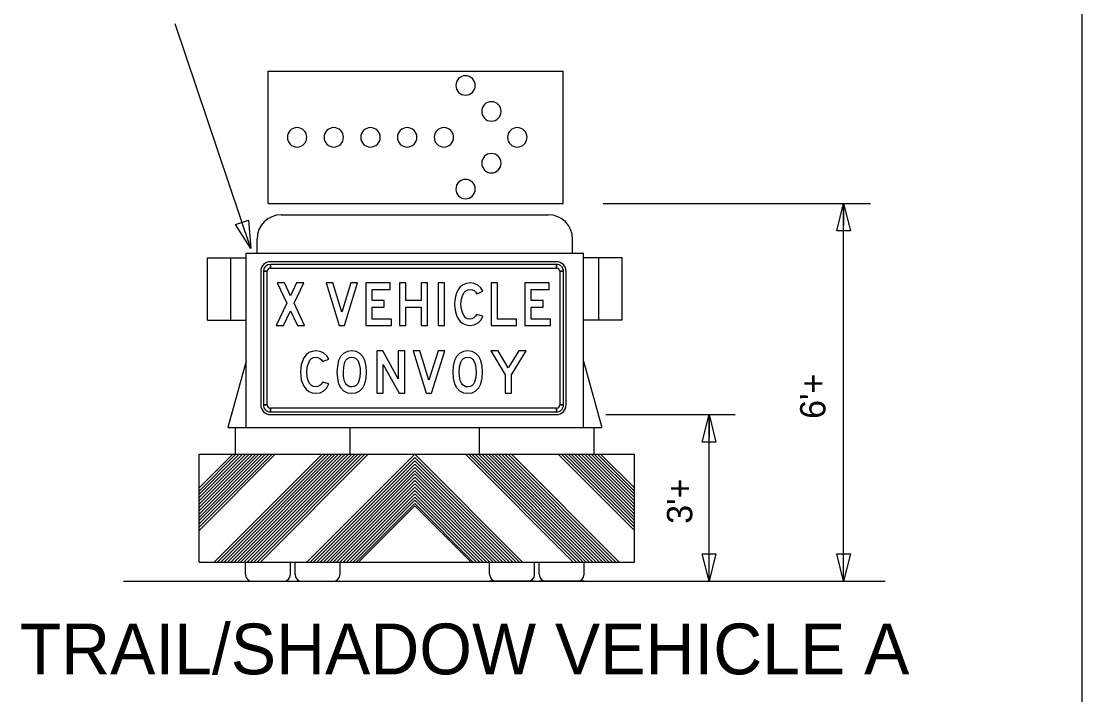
# Model space of a CAD drawing. Extents: x 1373848 to 1374003, y 380642 to 381248.
# Drawn here: x 1373929.4 to 1373954.48, y 381055.63 to 381071.55 of the extents above; entities that cross this region are included whole.
import ezdxf

# ---------------------------------------------------------------- set-up
doc = ezdxf.new("R2010")
doc.units = 0
doc.layers.add('Working Level 1', color=7, linetype='Continuous')

msp = doc.modelspace()

# ---------------------------------------------------------------- linework, layer by layer
at = {"layer": 'Working Level 1'}
for p, q in [((1373954.481, 381081.277), (1373954.481, 380977.045)), ((1373934.824, 381066.18), (1373933.038, 381071.487)), ((1373935.233, 381070.37), (1373942.211, 381070.37)), ((1373935.233, 381067.242), (1373935.233, 381070.37)), ((1373942.211, 381067.242), (1373942.211, 381070.37)), ((1373935.233, 381067.242), (1373942.211, 381067.242)), ((1373943.157, 381067.242), (1373949.484, 381067.242)), ((1373948.848, 381058.31), (1373948.848, 381067.242)), ((1373948.848, 381067.242), (1373948.848, 381066.718)), ((1373935.548, 381066.974), (1373941.862, 381066.974)), ((1373934.974, 381066.071), (1373934.974, 381066.4)), ((1373942.436, 381066.071), (1373942.436, 381066.4)), ((1373933.803, 381064.487), (1373933.803, 381065.954)), ((1373933.803, 381065.954), (1373934.714, 381065.954)), ((1373934.354, 381064.487), (1373934.354, 381065.954)), ((1373934.714, 381061.944), (1373934.714, 381066.071)), ((1373934.714, 381066.071), (1373942.696, 381066.071)), ((1373942.696, 381061.944), (1373942.696, 381066.071)), ((1373943.607, 381065.954), (1373942.696, 381065.954)), ((1373943.055, 381064.487), (1373943.055, 381065.954)), ((1373943.607, 381064.487), (1373943.607, 381065.954)), ((1373942.059, 381065.864), (1373935.288, 381065.864)), ((1373935.288, 381065.713), (1373935.288, 381065.801)), ((1373942.059, 381065.801), (1373942.059, 381065.713)), ((1373935.062, 381065.638), (1373935.062, 381062.478)), ((1373935.125, 381065.638), (1373935.213, 381065.638)), ((1373942.135, 381065.638), (1373942.222, 381065.638)), ((1373942.285, 381062.478), (1373942.285, 381065.638)), ((1373933.803, 381064.487), (1373934.714, 381064.487)), ((1373943.607, 381064.487), (1373942.696, 381064.487)), ((1373934.714, 381063.516), (1373934.282, 381061.944)), ((1373942.696, 381063.516), (1373943.128, 381061.944)), ((1373935.213, 381062.478), (1373935.125, 381062.478)), ((1373935.288, 381062.315), (1373935.288, 381062.403)), ((1373942.059, 381062.403), (1373942.059, 381062.315)), ((1373942.222, 381062.478), (1373942.135, 381062.478)), ((1373935.288, 381062.252), (1373942.059, 381062.252)), ((1373943.223, 381062.252), (1373946.284, 381062.252)), ((1373945.667, 381058.31), (1373945.667, 381062.252)), ((1373945.667, 381062.252), (1373945.667, 381061.72)), ((1373934.282, 381061.944), (1373943.128, 381061.944)), ((1373934.461, 381061.314), (1373934.461, 381061.944)), ((1373937.173, 381061.314), (1373937.173, 381061.933)), ((1373940.237, 381061.314), (1373940.237, 381061.933)), ((1373942.949, 381061.314), (1373942.949, 381061.944)), ((1373933.604, 381061.314), (1373943.899, 381061.314)), ((1373933.604, 381061.314), (1373943.899, 381061.314)), ((1373933.604, 381061.314), (1373943.899, 381061.314)), ((1373933.604, 381061.314), (1373943.899, 381061.314)), ((1373933.604, 381058.764), (1373933.604, 381061.314)), ((1373933.604, 381060.516), (1373934.402, 381061.314)), ((1373933.604, 381059.588), (1373935.33, 381061.314)), ((1373933.604, 381059.666), (1373935.252, 381061.314)), ((1373933.604, 381059.744), (1373935.174, 381061.314)), ((1373933.604, 381059.821), (1373935.097, 381061.314)), ((1373933.604, 381059.899), (1373935.019, 381061.314)), ((1373933.604, 381059.977), (1373934.941, 381061.314)), ((1373933.604, 381060.054), (1373934.864, 381061.314)), ((1373933.604, 381060.132), (1373934.786, 381061.314)), ((1373933.604, 381060.211), (1373934.707, 381061.314)), ((1373933.604, 381060.289), (1373934.629, 381061.314)), ((1373933.604, 381060.366), (1373934.552, 381061.314)), ((1373933.604, 381060.444), (1373934.474, 381061.314)), ((1373933.604, 381059.51), (1373935.405, 381061.312)), ((1373933.963, 381058.764), (1373936.513, 381061.314)), ((1373934.041, 381058.764), (1373936.591, 381061.314)), ((1373934.119, 381058.764), (1373936.669, 381061.314)), ((1373934.197, 381058.764), (1373936.747, 381061.314)), ((1373934.274, 381058.764), (1373936.824, 381061.314)), ((1373934.352, 381058.764), (1373936.902, 381061.314)), ((1373934.43, 381058.764), (1373936.98, 381061.314)), ((1373934.508, 381058.764), (1373937.058, 381061.314)), ((1373934.585, 381058.764), (1373937.135, 381061.314)), ((1373934.663, 381058.764), (1373937.213, 381061.314)), ((1373934.742, 381058.764), (1373937.291, 381061.314)), ((1373934.819, 381058.764), (1373937.368, 381061.314)), ((1373934.897, 381058.764), (1373937.446, 381061.314)), ((1373934.975, 381058.764), (1373937.523, 381061.313)), ((1373935.052, 381058.764), (1373937.602, 381061.314)), ((1373936.155, 381058.764), (1373938.705, 381061.314)), ((1373936.233, 381058.764), (1373938.705, 381061.236)), ((1373936.311, 381058.764), (1373938.705, 381061.158)), ((1373941.255, 381058.764), (1373938.705, 381061.314)), ((1373941.173, 381058.768), (1373938.705, 381061.236)), ((1373941.1, 381058.764), (1373938.705, 381061.158)), ((1373942.451, 381058.764), (1373939.901, 381061.314)), ((1373942.528, 381058.764), (1373939.98, 381061.313)), ((1373942.607, 381058.764), (1373940.057, 381061.314)), ((1373942.685, 381058.764), (1373940.135, 381061.314)), ((1373942.762, 381058.764), (1373940.212, 381061.314)), ((1373942.84, 381058.764), (1373940.29, 381061.314)), ((1373942.918, 381058.764), (1373940.368, 381061.314)), ((1373942.995, 381058.764), (1373940.445, 381061.314)), ((1373943.073, 381058.764), (1373940.523, 381061.314)), ((1373943.151, 381058.764), (1373940.601, 381061.314)), ((1373943.229, 381058.764), (1373940.679, 381061.314)), ((1373943.306, 381058.764), (1373940.756, 381061.314)), ((1373943.384, 381058.764), (1373940.834, 381061.314)), ((1373943.462, 381058.764), (1373940.913, 381061.314)), ((1373943.54, 381058.764), (1373940.99, 381061.314)), ((1373943.899, 381059.51), (1373942.098, 381061.312)), ((1373943.899, 381059.588), (1373942.173, 381061.314)), ((1373943.899, 381059.666), (1373942.251, 381061.314)), ((1373943.899, 381059.744), (1373942.329, 381061.314)), ((1373943.899, 381059.821), (1373942.406, 381061.314)), ((1373943.899, 381059.899), (1373942.484, 381061.314)), ((1373943.899, 381059.977), (1373942.563, 381061.314)), ((1373943.899, 381060.054), (1373942.64, 381061.314)), ((1373943.899, 381060.132), (1373942.718, 381061.314)), ((1373943.899, 381060.211), (1373942.796, 381061.314)), ((1373943.899, 381060.289), (1373942.874, 381061.314)), ((1373943.899, 381060.366), (1373942.951, 381061.314)), ((1373943.899, 381060.444), (1373943.029, 381061.314)), ((1373943.899, 381060.516), (1373943.101, 381061.314)), ((1373943.899, 381058.764), (1373943.899, 381061.314)), ((1373936.389, 381058.764), (1373938.705, 381061.08)), ((1373936.466, 381058.764), (1373938.705, 381061.003)), ((1373936.544, 381058.764), (1373938.705, 381060.925)), ((1373941.021, 381058.764), (1373938.705, 381061.08)), ((1373940.944, 381058.764), (1373938.705, 381061.003)), ((1373940.866, 381058.764), (1373938.705, 381060.925)), ((1373936.622, 381058.764), (1373938.705, 381060.847)), ((1373936.699, 381058.764), (1373938.705, 381060.77)), ((1373936.777, 381058.764), (1373938.705, 381060.692)), ((1373940.788, 381058.764), (1373938.705, 381060.847)), ((1373940.711, 381058.764), (1373938.705, 381060.77)), ((1373940.633, 381058.764), (1373938.705, 381060.692)), ((1373936.855, 381058.764), (1373938.705, 381060.614)), ((1373936.933, 381058.764), (1373938.705, 381060.536)), ((1373937.01, 381058.764), (1373938.705, 381060.459)), ((1373940.555, 381058.764), (1373938.705, 381060.614)), ((1373940.477, 381058.764), (1373938.705, 381060.536)), ((1373940.4, 381058.764), (1373938.705, 381060.459)), ((1373937.088, 381058.764), (1373938.705, 381060.38)), ((1373937.167, 381058.764), (1373938.705, 381060.302)), ((1373937.244, 381058.764), (1373938.705, 381060.225)), ((1373937.321, 381058.764), (1373938.705, 381060.148)), ((1373940.322, 381058.764), (1373938.705, 381060.38)), ((1373940.244, 381058.764), (1373938.705, 381060.302)), ((1373940.167, 381058.764), (1373938.705, 381060.225)), ((1373940.089, 381058.764), (1373938.705, 381060.148)), ((1373937.387, 381058.779), (1373938.705, 381060.097)), ((1373940.038, 381058.764), (1373938.705, 381060.097)), ((1373933.604, 381058.764), (1373943.899, 381058.764)), ((1373933.604, 381058.764), (1373943.899, 381058.764)), ((1373933.604, 381058.764), (1373943.899, 381058.764)), ((1373933.604, 381058.764), (1373943.899, 381058.764)), ((1373934.698, 381058.475), (1373934.698, 381058.764)), ((1373935.762, 381058.475), (1373935.762, 381058.764)), ((1373935.872, 381058.475), (1373935.872, 381058.764)), ((1373936.936, 381058.475), (1373936.936, 381058.764)), ((1373940.474, 381058.475), (1373940.474, 381058.764)), ((1373941.538, 381058.475), (1373941.538, 381058.764)), ((1373941.648, 381058.475), (1373941.648, 381058.764)), ((1373942.712, 381058.475), (1373942.712, 381058.764)), ((1373931.816, 381058.31), (1373949.828, 381058.31)), ((1373934.698, 381058.31), (1373935.762, 381058.31)), ((1373934.698, 381058.31), (1373935.762, 381058.31)), ((1373934.698, 381058.31), (1373935.762, 381058.31)), ((1373934.698, 381058.31), (1373935.762, 381058.31)), ((1373935.872, 381058.31), (1373936.936, 381058.31)), ((1373935.872, 381058.31), (1373936.936, 381058.31)), ((1373935.872, 381058.31), (1373936.936, 381058.31)), ((1373935.872, 381058.31), (1373936.936, 381058.31)), ((1373941.538, 381058.31), (1373940.474, 381058.31)), ((1373941.538, 381058.31), (1373940.474, 381058.31)), ((1373941.538, 381058.31), (1373940.474, 381058.31)), ((1373941.538, 381058.31), (1373940.474, 381058.31)), ((1373942.712, 381058.31), (1373941.648, 381058.31)), ((1373942.712, 381058.31), (1373941.648, 381058.31)), ((1373942.712, 381058.31), (1373941.648, 381058.31)), ((1373942.712, 381058.31), (1373941.648, 381058.31))]:
    msp.add_line(p, q, dxfattribs=at)
for points in [[(1373948.685, 381066.592), (1373948.848, 381067.242), (1373949.01, 381066.592)], [(1373934.771, 381066.848), (1373934.824, 381066.18), (1373934.463, 381066.744)], [(1373942.059, 381065.801), (1373935.288, 381065.801), (1373935.288, 381065.713), (1373942.059, 381065.713), (1373942.059, 381065.801)], [(1373935.125, 381065.638), (1373935.125, 381062.478), (1373935.213, 381062.478), (1373935.213, 381065.638), (1373935.125, 381065.638)], [(1373942.222, 381062.478), (1373942.222, 381065.638), (1373942.135, 381065.638), (1373942.135, 381062.478), (1373942.222, 381062.478)], [(1373936.098, 381064.359), (1373935.849, 381064.884), (1373936.078, 381065.362), (1373935.91, 381065.362), (1373935.765, 381065.059), (1373935.62, 381065.362), (1373935.452, 381065.362), (1373935.681, 381064.883), (1373935.429, 381064.359), (1373935.597, 381064.359), (1373935.764, 381064.707), (1373935.931, 381064.359)], [(1373937.352, 381065.362), (1373937.193, 381065.362), (1373936.978, 381064.669), (1373936.763, 381065.362), (1373936.605, 381065.362), (1373936.915, 381064.359), (1373937.04, 381064.359)], [(1373938.152, 381064.51), (1373937.696, 381064.51), (1373937.696, 381064.794), (1373937.98, 381064.794), (1373937.98, 381064.946), (1373937.696, 381064.946), (1373937.696, 381065.211), (1373938.121, 381065.211), (1373938.121, 381065.362), (1373937.545, 381065.362), (1373937.545, 381064.359), (1373938.152, 381064.359)], [(1373939.007, 381064.359), (1373939.007, 381065.362), (1373938.855, 381065.362), (1373938.855, 381064.946), (1373938.496, 381064.946), (1373938.496, 381065.362), (1373938.344, 381065.362), (1373938.344, 381064.359), (1373938.496, 381064.359), (1373938.496, 381064.794), (1373938.855, 381064.794), (1373938.855, 381064.359)], [(1373939.405, 381064.359), (1373939.405, 381065.362), (1373939.254, 381065.362), (1373939.254, 381064.359)], [(1373940.315, 381064.581), (1373940.163, 381064.62), (1373940.141, 381064.576), (1373940.104, 381064.541), (1373940.057, 381064.518), (1373940.005, 381064.51), (1373939.952, 381064.518), (1373939.907, 381064.542), (1373939.869, 381064.582), (1373939.838, 381064.638), (1373939.807, 381064.741), (1373939.797, 381064.86), (1373939.807, 381064.98), (1373939.839, 381065.084), (1373939.871, 381065.139), (1373939.91, 381065.179), (1373939.956, 381065.203), (1373940.01, 381065.211), (1373940.06, 381065.203), (1373940.106, 381065.183), (1373940.144, 381065.15), (1373940.17, 381065.108), (1373940.315, 381065.165), (1373940.266, 381065.245), (1373940.194, 381065.308), (1373940.107, 381065.348), (1373940.012, 381065.362), (1373939.924, 381065.351), (1373939.847, 381065.32), (1373939.781, 381065.268), (1373939.726, 381065.195), (1373939.691, 381065.122), (1373939.666, 381065.043), (1373939.651, 381064.955), (1373939.646, 381064.861), (1373939.65, 381064.767), (1373939.665, 381064.68), (1373939.69, 381064.6), (1373939.725, 381064.528), (1373939.779, 381064.454), (1373939.844, 381064.401), (1373939.92, 381064.369), (1373940.007, 381064.359), (1373940.109, 381064.374), (1373940.201, 381064.421), (1373940.272, 381064.492)], [(1373941.114, 381064.359), (1373941.114, 381064.51), (1373940.659, 381064.51), (1373940.659, 381065.362), (1373940.508, 381065.362), (1373940.508, 381064.359)], [(1373941.914, 381064.51), (1373941.458, 381064.51), (1373941.458, 381064.794), (1373941.742, 381064.794), (1373941.742, 381064.946), (1373941.458, 381064.946), (1373941.458, 381065.211), (1373941.883, 381065.211), (1373941.883, 381065.362), (1373941.307, 381065.362), (1373941.307, 381064.359), (1373941.914, 381064.359)], [(1373936.671, 381062.976), (1373936.519, 381063.015), (1373936.496, 381062.971), (1373936.46, 381062.936), (1373936.413, 381062.913), (1373936.36, 381062.905), (1373936.308, 381062.913), (1373936.262, 381062.937), (1373936.224, 381062.977), (1373936.194, 381063.033), (1373936.162, 381063.136), (1373936.152, 381063.255), (1373936.163, 381063.375), (1373936.195, 381063.479), (1373936.226, 381063.534), (1373936.265, 381063.573), (1373936.312, 381063.597), (1373936.365, 381063.605), (1373936.415, 381063.598), (1373936.461, 381063.578), (1373936.499, 381063.545), (1373936.525, 381063.503), (1373936.671, 381063.56), (1373936.621, 381063.64), (1373936.55, 381063.703), (1373936.463, 381063.743), (1373936.368, 381063.757), (1373936.279, 381063.746), (1373936.202, 381063.715), (1373936.137, 381063.663), (1373936.082, 381063.59), (1373936.046, 381063.517), (1373936.021, 381063.437), (1373936.006, 381063.35), (1373936.001, 381063.256), (1373936.006, 381063.162), (1373936.021, 381063.075), (1373936.046, 381062.995), (1373936.081, 381062.923), (1373936.134, 381062.849), (1373936.199, 381062.796), (1373936.276, 381062.764), (1373936.363, 381062.754), (1373936.465, 381062.769), (1373936.556, 381062.815), (1373936.628, 381062.887)], [(1373937.563, 381063.256), (1373937.553, 381063.399), (1373937.523, 381063.533), (1373937.477, 381063.623), (1373937.406, 381063.695), (1373937.315, 381063.741), (1373937.213, 381063.757), (1373937.111, 381063.741), (1373937.02, 381063.695), (1373936.949, 381063.623), (1373936.904, 381063.532), (1373936.873, 381063.398), (1373936.863, 381063.256), (1373936.873, 381063.114), (1373936.904, 381062.979), (1373936.949, 381062.888), (1373937.02, 381062.816), (1373937.111, 381062.769), (1373937.213, 381062.754), (1373937.314, 381062.769), (1373937.405, 381062.815), (1373937.476, 381062.887), (1373937.522, 381062.978), (1373937.553, 381063.112)], [(1373938.466, 381062.754), (1373938.466, 381063.757), (1373938.315, 381063.757), (1373938.315, 381063.097), (1373937.949, 381063.757), (1373937.804, 381063.757), (1373937.804, 381062.754), (1373937.955, 381062.754), (1373937.955, 381063.434), (1373938.332, 381062.754)], [(1373939.413, 381063.757), (1373939.254, 381063.757), (1373939.039, 381063.064), (1373938.824, 381063.757), (1373938.666, 381063.757), (1373938.977, 381062.754), (1373939.101, 381062.754)], [(1373940.306, 381063.256), (1373940.296, 381063.399), (1373940.266, 381063.533), (1373940.221, 381063.623), (1373940.149, 381063.695), (1373940.058, 381063.741), (1373939.956, 381063.757), (1373939.854, 381063.741), (1373939.764, 381063.695), (1373939.692, 381063.623), (1373939.647, 381063.532), (1373939.616, 381063.398), (1373939.606, 381063.256), (1373939.616, 381063.114), (1373939.647, 381062.979), (1373939.692, 381062.888), (1373939.764, 381062.816), (1373939.854, 381062.769), (1373939.956, 381062.754), (1373940.058, 381062.769), (1373940.148, 381062.815), (1373940.22, 381062.887), (1373940.265, 381062.978), (1373940.296, 381063.112)], [(1373941.341, 381063.757), (1373941.163, 381063.757), (1373940.917, 381063.356), (1373940.676, 381063.757), (1373940.5, 381063.757), (1373940.84, 381063.193), (1373940.84, 381062.754), (1373940.992, 381062.754), (1373940.992, 381063.189)], [(1373937.412, 381063.255), (1373937.403, 381063.133), (1373937.377, 381063.02), (1373937.352, 381062.973), (1373937.315, 381062.936), (1373937.267, 381062.913), (1373937.214, 381062.905), (1373937.167, 381062.91), (1373937.126, 381062.927), (1373937.092, 381062.954), (1373937.064, 381062.993), (1373937.042, 381063.042), (1373937.027, 381063.102), (1373937.017, 381063.173), (1373937.015, 381063.255), (1373937.023, 381063.377), (1373937.05, 381063.489), (1373937.074, 381063.537), (1373937.112, 381063.574), (1373937.159, 381063.597), (1373937.214, 381063.605), (1373937.26, 381063.6), (1373937.3, 381063.584), (1373937.334, 381063.556), (1373937.362, 381063.518), (1373937.384, 381063.469), (1373937.4, 381063.409), (1373937.409, 381063.337)], [(1373940.155, 381063.255), (1373940.146, 381063.133), (1373940.12, 381063.02), (1373940.095, 381062.973), (1373940.058, 381062.936), (1373940.011, 381062.913), (1373939.957, 381062.905), (1373939.91, 381062.91), (1373939.869, 381062.927), (1373939.835, 381062.954), (1373939.807, 381062.993), (1373939.785, 381063.042), (1373939.77, 381063.102), (1373939.761, 381063.173), (1373939.758, 381063.255), (1373939.766, 381063.377), (1373939.793, 381063.489), (1373939.817, 381063.537), (1373939.855, 381063.574), (1373939.902, 381063.597), (1373939.957, 381063.605), (1373940.003, 381063.6), (1373940.043, 381063.584), (1373940.077, 381063.556), (1373940.105, 381063.518), (1373940.127, 381063.469), (1373940.143, 381063.409), (1373940.152, 381063.337)], [(1373935.288, 381062.315), (1373942.059, 381062.315), (1373942.059, 381062.403), (1373935.288, 381062.403), (1373935.288, 381062.315)], [(1373945.504, 381061.602), (1373945.667, 381062.252), (1373945.829, 381061.602)], [(1373945.829, 381058.96), (1373945.667, 381058.31), (1373945.504, 381058.96)], [(1373949.01, 381058.96), (1373948.848, 381058.31), (1373948.685, 381058.96)]]:
    msp.add_lwpolyline(points, close=True, dxfattribs=at)
for centre, radius, start, end in [((1373939.905, 381070.032), 0.23, 0, 180), ((1373939.905, 381070.032), 0.23, 180, 0), ((1373940.517, 381069.419), 0.23, 0, 180), ((1373940.517, 381069.419), 0.23, 180, 0), ((1373935.921, 381068.806), 0.23, 0, 180), ((1373936.789, 381068.806), 0.23, 0, 180), ((1373937.657, 381068.806), 0.23, 0, 180), ((1373938.525, 381068.806), 0.23, 0, 180), ((1373939.393, 381068.806), 0.23, 0, 180), ((1373941.129, 381068.806), 0.23, 0, 180), ((1373935.921, 381068.806), 0.23, 180, 0), ((1373936.789, 381068.806), 0.23, 180, 0), ((1373937.657, 381068.806), 0.23, 180, 0), ((1373938.525, 381068.806), 0.23, 180, 0), ((1373939.393, 381068.806), 0.23, 180, 0), ((1373941.129, 381068.806), 0.23, 180, 0), ((1373940.517, 381068.194), 0.23, 0, 180), ((1373940.517, 381068.194), 0.23, 180, 0), ((1373939.905, 381067.582), 0.23, 0, 180), ((1373939.905, 381067.582), 0.23, 180, 0), ((1373935.548, 381066.4), 0.574, 90, 180), ((1373941.862, 381066.4), 0.574, 0, 90), ((1373935.288, 381065.638), 0.226, 90.0002, 179.9998), ((1373935.288, 381065.638), 0.163, 90.0002, 179.9998), ((1373935.288, 381065.638), 0.0752, 90.0002, 179.9998), ((1373942.059, 381065.638), 0.226, 0, 90.0002), ((1373942.059, 381065.638), 0.163, 0, 90.0002), ((1373942.059, 381065.638), 0.0752, 0, 90.0002), ((1373935.288, 381062.478), 0.226, 179.9998, 270.0001), ((1373935.288, 381062.478), 0.163, 179.9998, 270.0001), ((1373935.288, 381062.478), 0.0752, 179.9998, 270.0001), ((1373942.059, 381062.478), 0.226, 270.0001, 0.0003), ((1373942.059, 381062.478), 0.163, 270.0001, 0.0003), ((1373942.059, 381062.478), 0.0752, 270.0001, 0.0003), ((1373934.863, 381058.475), 0.165, 180, 270), ((1373935.597, 381058.475), 0.165, 270, 0), ((1373936.037, 381058.475), 0.165, 180, 270), ((1373936.771, 381058.475), 0.165, 270, 0), ((1373940.639, 381058.475), 0.165, 180, 270), ((1373941.373, 381058.475), 0.165, 270, 0), ((1373941.813, 381058.475), 0.165, 180, 270), ((1373942.547, 381058.475), 0.165, 270, 0)]:
    msp.add_arc(centre, radius, start, end, dxfattribs=at)

# ---------------------------------------------------------------- texts
for s, p in [("6'+", (1373948.418, 381062.15)), ("3'+", (1373945.268, 381059.669))]:
    msp.add_text(s, height=0.6, rotation=90, dxfattribs=at).set_placement(p)
msp.add_text('TRAIL/SHADOW VEHICLE A', height=1.2, dxfattribs=at).set_placement((1373929.359, 381056.11))

doc.saveas('drawing.dxf')
